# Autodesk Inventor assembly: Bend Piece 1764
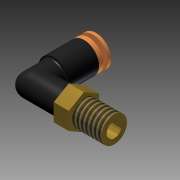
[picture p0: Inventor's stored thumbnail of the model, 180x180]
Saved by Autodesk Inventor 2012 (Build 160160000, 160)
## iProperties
Created: 2010-02
Part Number: Bend Piece 1764
Document SubType Name: Assembly
Designer: jgehrig
Author: jgehrig
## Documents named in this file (4)
- R:\CAD Archives\Pneumatics_1764\Pneumatics_Bend_Piece_1764\Pneumatic_Bend_Piece_1764.iam
- R:\CAD Archives\Pneumatics_1764\Pneumatics_Bend_Piece_1764\Pneumatic_Bend_Piece_1764.ipt
- R:\CAD Archives\Pneumatics_1764\Pneumatics_Bend_Piece_1764\Pneumatic_Screw_Part_1764.ipt
- R:\CAD Archives\Pneumatics_1764\Pneumatics_Bend_Piece_1764\Pneumatic_Screw_Part_2_1764.ipt
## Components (3 placed, 3 different names)
1. Pneumatic_Bend_Piece_1764:1 — Insert:1, Insert:2
2. Pneumatic_Screw_Part_1764:1 — Insert:2
3. Pneumatic_Screw_Part_2_1764:1 — Insert:1
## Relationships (2: Insert 2)
- Insert:1: Pneumatic_Bend_Piece_1764:1 ↔ Pneumatic_Screw_Part_2_1764:1
- Insert:2: Pneumatic_Bend_Piece_1764:1 ↔ Pneumatic_Screw_Part_1764:1
